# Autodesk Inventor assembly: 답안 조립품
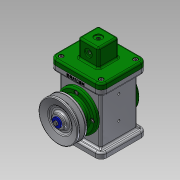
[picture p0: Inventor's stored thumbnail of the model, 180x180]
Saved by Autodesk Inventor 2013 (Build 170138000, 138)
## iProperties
Created: 2017-08
Part Number: 답안 조립품
Document SubType Name: Assembly
Designer: Administrator
Author: Administrator
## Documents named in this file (18)
- C:\Documents and Settings\Administrator\바탕 화면\470808V1023\470808V1023\답안 조립품.iam
- C:\Documents and Settings\Administrator\바탕 화면\470808V1023\덮개.ipt
- C:\Documents and Settings\Administrator\바탕 화면\470808V1023\뒤커버.ipt
- C:\Documents and Settings\Administrator\바탕 화면\470808V1023\링크.ipt
- C:\Documents and Settings\Administrator\바탕 화면\470808V1023\베어링 17 x 40 x 12.ipt
- C:\Documents and Settings\Administrator\바탕 화면\470808V1023\본체.ipt
- C:\Documents and Settings\Administrator\바탕 화면\470808V1023\볼트 M4 x 8.ipt
- C:\Documents and Settings\Administrator\바탕 화면\470808V1023\볼트 M4 x 10.ipt
- C:\Documents and Settings\Administrator\바탕 화면\470808V1023\슬라이더.ipt
- C:\Documents and Settings\Administrator\바탕 화면\470808V1023\앞커버.ipt
- C:\Documents and Settings\Administrator\바탕 화면\470808V1023\오일 실 17 30 8.ipt
- C:\Documents and Settings\Administrator\바탕 화면\470808V1023\와셔 4x16.ipt
- C:\Documents and Settings\Administrator\바탕 화면\470808V1023\클레비스 핀 6 x 22.ipt
- 클레비스 핀 6 x 22.ipt
- C:\Documents and Settings\Administrator\바탕 화면\470808V1023\키 4 x 4 x 12.ipt
- C:\Documents and Settings\Administrator\바탕 화면\470808V1023\편심축.ipt
- C:\Documents and Settings\Administrator\바탕 화면\470808V1023\E-링.ipt
- C:\Documents and Settings\Administrator\바탕 화면\470808V1023\V-벨트풀리.ipt
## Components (2 placed, 2 different names)
1. E-링:1
2. V-벨트풀리:1 — 플러쉬:3
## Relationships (1: Flush 1)
- 플러쉬:3 [Flush]: V-벨트풀리:1
